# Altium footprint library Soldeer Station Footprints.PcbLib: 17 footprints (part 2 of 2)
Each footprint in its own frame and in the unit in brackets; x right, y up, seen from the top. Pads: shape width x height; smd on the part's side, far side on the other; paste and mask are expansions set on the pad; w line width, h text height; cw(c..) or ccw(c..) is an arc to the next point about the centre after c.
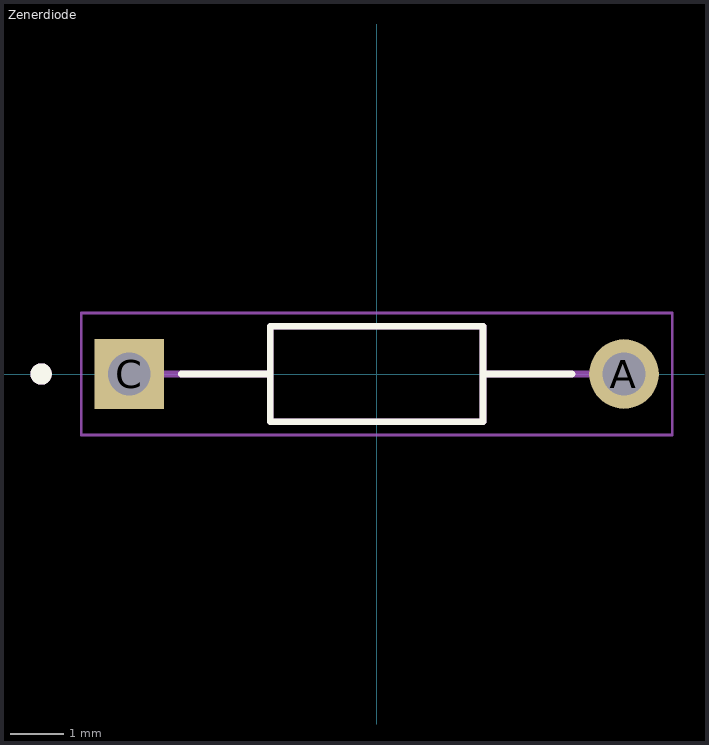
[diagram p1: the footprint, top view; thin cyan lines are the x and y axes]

## Zenerdiode [mm]
height 2.28
pads (2):
  round 1.308 hole 0.8: A(4.64,0)
  rect 1.308x1.308 / inner round 1.308 / far side rect 1.308x1.308 hole 0.8: C(-4.64,0)
Top Overlay:
  circle w0.2: c-6.294,0 r0.1
  lines w0.127: -3.666,0 -1.995,0 ; 3.666,0 1.995,0 ; -1.995,0 -1.995,0.895 1.995,0.895 1.995,0 ; -1.995,0 -1.995,-0.895 1.995,-0.895 1.995,0
Mechanical 13:
  circle w0.2: c-6.294,0 r0.1
  lines w0.127: -4.64,0 -1.995,0 ; 4.64,0 1.995,0 ; -1.995,0 -1.995,0.895 1.995,0.895 1.995,0 ; -1.995,0 -1.995,-0.895 1.995,-0.895 1.995,0
Mechanical 15:
  lines w0.05: -5.544,-1.145 -5.544,1.145 5.544,1.145 5.544,-1.145 -5.544,-1.145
